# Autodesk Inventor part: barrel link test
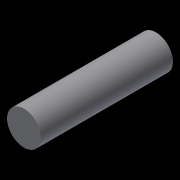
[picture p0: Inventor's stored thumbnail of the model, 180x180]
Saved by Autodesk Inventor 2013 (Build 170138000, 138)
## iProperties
Created: 2013-01
Part Number: barrel link test
Material: Generic
Document SubType Name: Modeling
Designer: John
Density: 1 g/cm^3
Author: John
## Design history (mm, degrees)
sketch "Sketch1"
  geometry: C1 r 2.603 at (0, 0); 1 further point
  constraints: 1 centre point, 1 coincident
  dimensions: "d0" = 5.207 diameter of C1
extrude "Extrusion1" new body sketch "Sketch1" distance "d1" = 20.32; taper "d2" = 0 deg
body "Solid1"
